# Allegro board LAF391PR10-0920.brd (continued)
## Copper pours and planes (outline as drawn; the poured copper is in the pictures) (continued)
BOOT1_ISL9538 on BOTTOM (solid shape): 31.36,42.39 31.36,41.38 31.21,41.23 31.21,40.72 31.36,40.57 31.71,40.57 31.84,40.43 31.84,39.52 31.74,39.42 30.88,39.42 30.85,39.44 30.85,40.65 30.78,40.73 30.77,40.84 30.73,40.94 30.73,41.15 31.15,41.57 31.15,42.38 31.21,42.44 31.31,42.44
BOOT2_ISL9538 on BOTTOM (solid shape): 34.54,44.47 34.85,44.47 35.02,44.3 35.02,43.57 35.06,43.57 35.12,43.51 35.66,43.51 35.72,43.45 35.72,42.55 35.72,42.53 35.03,42.53 34.93,42.64 34.93,43.04 34.7,43.27 34.7,43.55 34.75,43.74 34.7,43.93 34.7,43.95 34.54,44.11 34.46,44.11 34.37,44.12 34.28,44.11 32.67,44.11 32.62,44.15 32.62,44.28 32.68,44.35 33.95,44.35 34.07,44.47 34.31,44.47 34.32,44.47 34.37,44.47 34.43,44.48 34.54,44.48
BST_3V on BOTTOM (solid shape): 142.17,109.9 142.17,107.77 142.09,107.69 141.96,107.69 141.09,108.57 141.09,109.9 141.1,109.91 142.16,109.91
BST_5V on BOTTOM (solid shape): 45.15,45.68 45.15,44.73 45.09,44.67 44.51,44.67 44.39,44.79 44.39,45.23 44.21,45.41 43.06,45.41 42.96,45.51 42.96,45.7 43.05,45.79 45.04,45.79
BST_+1VALWP on BOTTOM (solid shape): 159.68,104.38 159.68,104.26 158.21,102.79 157.49,102.79 157.43,102.84 157.43,103.81 157.51,103.88 157.97,103.88 158.55,104.46 159.6,104.46
BST_+1VALWP_C on BOTTOM (solid shape): 156.85,103.75 156.85,102.14 156.26,101.55 155.38,101.55 155.3,101.63 155.3,102.29 155.99,102.98 155.99,103.71 156.09,103.81 156.79,103.81
CPU_B+ on BOTTOM (solid shape): 70.29,60.68 70.29,59.17 70.79,58.66 70.79,57.45 70.25,56.91 66.19,56.91 65.97,56.69 65.97,54.24 66.15,54.06 66.15,51.21 66.05,51.11 65.02,51.11 64.95,51.18 64.95,52.63 64.84,52.74 64.03,52.74 63.86,52.92 63.86,53.27 63.61,53.52 62.67,53.52 62.62,53.57 62.62,54.8 62.44,54.98 61.09,54.98 60.91,55.16 60.91,57.62 60.99,57.69 63.93,57.69 64.19,57.95 68.25,57.95 68.26,57.89 68.27,57.84 68.3,57.78 68.32,57.74 68.36,57.69 68.4,57.66 68.45,57.63 68.5,57.6 68.55,57.59 68.61,57.58 68.66,57.58 68.72,57.59 68.77,57.6 68.82,57.63 68.87,57.66 68.91,57.69 68.95,57.74 68.97,57.78 69,57.84 69.01,57.89 69.02,57.95 69.01,58 69,58.06 68.99,58.11 68.96,58.16 68.93,58.2 68.89,58.24 68.85,58.28 68.8,58.3 68.75,58.32 68.69,58.34 68.64,58.34 68.58,58.34 68.53,58.32 68.47,58.3 68.42,58.28 68.38,58.24 68.34,58.2 68.31,58.16 68.28,58.11 68.27,58.06 68.26,58 68.25,57.95 64.19,57.95 65.54,59.29 65.54,60.61 65.82,60.9 70.07,60.9
CPU_B+ on IN1 (solid shape): 66.26,56.75 66.26,51.98 66.16,51.88 64.11,51.88 63.29,52.71 63.29,56.95 63.61,57.26 65.75,57.26
CPU_B+ on IN2 (solid shape): 66.26,56.75 66.26,51.98 66.16,51.88 64.13,51.88 63.29,52.72 63.29,56.95 63.62,57.28 65.73,57.28
CPU_B+ on TOP: 72.38,84.32 73.21,85.15 74.62,85.15 75.37,85.9 82.1,85.9 84.89,88.69 87.69,88.69 87.69,87.68 85.65,87.68 82.86,84.88 76.19,84.88 75.37,84.06 75.37,78.8 75.09,78.52 72.75,78.52 72.38,78.89
CPU_B+ on TOP: 68.22,57.75 68.37,57.59 68.83,57.59 69.04,57.81 69.04,58.54 69.22,58.72 70.73,58.72 71.43,59.42 73.95,59.42 74.32,59.05 74.98,59.05 75.17,59.23 78.22,59.23 78.48,58.97 78.48,58.47 77.97,57.96 77.39,57.96 76.66,57.23 74.66,57.23 74.46,57.43 71.96,57.43 71.81,57.27 71.81,57.01 71.49,56.69 66.29,56.69 66.07,56.47 66.07,54.19 66.27,53.98 66.27,51.95 66.12,51.8 60.06,51.8 59.81,52.05 59.81,54.15 59.88,54.23 59.88,54.38 60.44,54.94 60.55,54.94 60.58,54.97 61.71,54.97 64.49,57.75
CPU_B+ on BOTTOM: 78.16,59.95 78.66,59.95 79.1,60.39 79.12,60.39 79.22,60.41 79.32,60.45 81.82,60.45 81.9,60.37 81.9,60.36 81.9,59.25 81.87,59.22 80.54,59.22 80.41,59.09 80.41,58.32 80.24,58.15 79.53,58.15 79.13,57.75 79.11,57.74 79.11,57.09 78.97,56.95 75.15,56.95 74.62,57.47 74.62,58.32 75.53,59.23 76.51,59.23 76.52,59.22 77.92,59.22 77.97,59.27 77.97,59.76
CPU_B+ on BOTTOM: 74.08,78.03 74.07,78.05 74.07,79.5 74,79.56 73.26,79.56 73.1,79.72 73.1,82.9 72.94,83.05 72.94,86.61 73.28,86.95 74.88,86.95 75.34,86.49 75.34,83.78 75.34,83.77 75.34,78.07 75.31,78.03
CPU_B+ on IN1: 73.45,78.2 73.16,78.49 73.16,81.22 73.97,82.03 74.93,82.03 75.31,81.64 75.31,78.48 75.03,78.2
CPU_B+ on IN1: 80.05,59.11 81.31,59.11 81.43,59.23 81.43,60.28 81.27,60.44 80.26,60.44 79.93,60.11 79.93,59.23
CPU_B+ on IN2: 74.73,57.34 80.76,57.34 81.44,58.02 81.44,60.22 81.22,60.44 79.89,60.44 78.71,59.25 75.22,59.25 74.41,58.45 74.41,57.66
CPU_B+ on IN2: 75.23,78.51 73.45,78.51 73.04,78.93 73.04,80.71 74.41,82.09 75.02,82.09 75.46,81.64 75.46,78.75
CPU_B+ on IN3: 64.8,53.56 66.07,53.56 66.24,53.39 66.24,51.31 66.03,51.11 64.93,51.11 64.73,51.31 64.73,53.49
CPU_B+ on IN3: 73.87,56.56 70.29,56.56 70.28,56.57 69.35,56.57 69.05,56.88 69.05,59.89 74.05,64.89 74.05,66.47 74.35,66.77 74.35,71.29 71.94,73.71 71.94,82.08 72.45,82.6 75.02,82.6 75.23,82.4 75.23,77.03 76.39,75.87 76.89,75.87 78.67,74.09 78.67,64.39 78.44,64.16 78.44,63.14 78.67,62.91 78.67,60.61 78.8,60.48 81.12,60.48 81.41,60.18 81.41,57.97 80.76,57.31 74.29,57.31 74.06,57.09 74.06,56.75
CPU_B+ on IN4: 72.59,78.42 70.79,76.63 68,76.63 66.86,75.48 64.32,75.48 63.17,76.63 61.9,76.63 56.19,70.91 56.19,60.37 57.08,59.48 63.3,59.48 63.68,59.1 63.68,55.95 63.19,55.46 63.19,52.32 64.15,51.35 66.04,51.35 66.05,51.36 66.2,51.36 66.53,51.69 66.53,52.93 66.81,53.21 66.81,56.57 67.21,56.98 70.72,56.98 71.12,57.38 79.84,57.38 81.36,58.9 81.36,60.25 81.22,60.39 80.18,60.39 79.99,60.2 78.05,60.2 77.82,59.97 76.25,59.97 76.03,60.19 76.03,60.49 75.95,60.58 69.58,60.58 68.26,61.9 65.87,61.9 63.3,64.47 63.3,71.55 62.29,72.56 62.29,73.39 62.63,73.74 67.46,73.74 67.87,73.33 71.81,73.33 74.3,75.82 74.3,77.47 74.54,77.71 75.05,77.71 75.24,77.9 75.24,81.89 74.45,82.67 73.6,82.67 72.59,81.66 ; 1 cut-out
FB_+1VALWP on BOTTOM (solid shape): 164.45,107.1 164.45,104.75 164.18,104.48 162.92,104.48 162.76,104.64 161.95,104.64 161.88,104.71 161.88,104.82 161.95,104.9 162.74,104.9 162.78,104.86 163.47,104.86 163.75,105.14 163.75,107.08 163.83,107.16 164.39,107.16
GT_SW on TOP (solid shape): 73.84,51.55 73.84,50.28 73.72,50.15 72.32,50.15 72.13,50.34 72.13,52.05 72.19,52.12 73.27,52.12
GT_SW on BOTTOM: 72.11,51.3 72.11,52.02 72.15,52.05 73.28,52.05 73.35,52.12 73.35,53.46 73.29,53.51 69.24,53.51 68.81,53.08 68.81,49.28 68.67,49.14 67.39,49.14 67.32,49.06 67.32,47.59 67.47,47.44 73.77,47.44 73.94,47.61 73.94,51.14 73.78,51.3
IA_SNUB1 on TOP (solid shape): 77.92,64.56 77.92,61.82 77.71,61.62 76.92,61.62 76.76,61.78 76.76,61.9 76.79,62.05 76.76,62.19 76.76,62.55 76.78,62.66 76.76,62.77 76.76,64.04 76.83,64.25 76.77,64.46 76.76,64.48 76.76,64.58 76.84,64.66 77.81,64.66
IA_SNUB2 on TOP (solid shape): 81.34,82.47 81.34,80.95 81.08,80.69 79.43,80.69 79.18,80.95 79.18,81.71 80.19,82.72 81.08,82.72
IA_SW1 on BOTTOM (solid shape): 82.48,67.42 82.48,66.4 82.5,66.38 83.26,66.38 83.3,66.41 83.3,67.54 83.43,67.67 84.89,67.67 85.46,67.1 85.46,63.33 85.46,63.32 85.46,61.95 85.06,61.55 84.08,61.55 83.98,61.65 83.98,62.81 83.74,63.05 80.04,63.05 79.98,63.12 79.98,64 80.11,64.14 80.11,64.14 80.31,64.35 83.2,64.35 83.21,64.29 83.22,64.24 83.24,64.18 83.27,64.14 83.31,64.09 83.35,64.06 83.4,64.03 83.45,64 83.5,63.99 83.56,63.98 83.61,63.98 83.67,63.99 83.72,64 83.77,64.03 83.82,64.06 83.86,64.09 83.89,64.14 83.92,64.18 83.94,64.24 83.96,64.29 83.97,64.35 83.96,64.4 83.95,64.46 83.93,64.51 83.91,64.56 83.88,64.6 83.84,64.64 83.79,64.68 83.75,64.71 83.69,64.73 83.64,64.74 83.58,64.74 83.53,64.74 83.47,64.73 83.42,64.71 83.37,64.68 83.33,64.64 83.29,64.6 83.26,64.56 83.23,64.51 83.21,64.46 83.2,64.4 83.2,64.35 80.31,64.35 80.73,64.76 80.79,64.82 80.79,65.78 80.8,65.82 80.8,65.88 80.8,65.95 80.79,65.98 80.79,67.07 80.79,67.07 80.79,67.45 81.02,67.67 82.22,67.67
IA_SW1 on TOP: 82.1,64.65 81.48,64.65 81.3,64.83 79.49,64.83 79.32,64.67 79.32,63.1 79.43,62.99 79.43,62.98 82.2,62.98 82.27,63.04 82.27,64.49
IA_SW2 on TOP (solid shape): 85.27,82.47 85.27,80.82 85.02,80.56 83.11,80.56 82.86,80.82 82.86,82.47 83.11,82.72 85.02,82.72
IA_SW2 on BOTTOM (solid shape): 85.27,82.9 85.27,80.44 85.02,80.18 83.37,80.18 83.32,80.23 83.32,81.8 83.3,81.82 82.51,81.82 82.51,80.47 82.1,80.06 80.89,80.06 80.32,79.48 80.32,76.38 78.8,74.87 76.69,74.87 76.56,75 76.56,75.9 77.91,75.9 78.03,76.03 78.03,80.83 78.47,81.27 78.47,82.95 78.82,83.3 84.87,83.3
INT_SPK_L+ on TOP (solid shape): 266.09,27.3 266.09,25.74 265.96,25.61 265.9,25.61 265.29,25 265.29,22.71 265.22,22.65 265.11,22.65 265.06,22.7 265.06,24.21 264.87,24.39 264.87,25.24 265.17,25.54 265.17,25.98 265.45,26.26 265.45,27.31 265.5,27.37 266.03,27.37
INT_SPK_L- on TOP (solid shape): 264.09,25.62 264.71,25 264.71,24.36 264.88,24.19 264.88,22.72 264.81,22.65 264.73,22.65 264.67,22.7 264.67,22.79 264.68,22.79 264.68,24.1 264.18,24.59 264.18,24.7 263.53,25.36 263.53,27.29 263.58,27.34 264.09,27.34
INT_SPK_R+ on TOP (solid shape): 261.25,26.61 261.19,26.41 261.25,26.21 261.26,26.2 261.26,26.17 261.48,25.94 261.48,25.67 261.71,25.44 261.75,25.4 262.51,25.4 264.09,23.83 264.09,22.71 264.03,22.65 263.93,22.65 263.86,22.72 263.86,23.72 263.17,24.41 262.65,24.41 262.16,24.9 261.23,24.9 260.75,25.38 260.75,27.29 260.8,27.35 261.25,27.35
INT_SPK_R- on TOP (solid shape): 263.36,27.3 263.36,25.28 263.93,24.71 263.93,24.64 264.49,24.08 264.49,22.71 264.42,22.65 264.33,22.65 264.27,22.7 264.27,23.85 262.68,25.44 262.68,27.32 262.72,27.36 263.31,27.36
INT_SPKR_L+ on TOP (solid shape): 267.06,28.01 267.06,26.7 266.9,26.54 266.28,26.54 266.23,26.58 266.23,27.39 266.11,27.51 265.49,27.51 265.4,27.6 265.4,28.43 265.57,28.6 266.47,28.6
INT_SPKR_L+ on BOTTOM (solid shape): 257.88,22.15 257.88,21.83 257.65,21.6 256.44,21.6 256.43,21.6 255.59,21.6 255.17,21.18 255.08,21.04 255.07,20.86 255.07,20.62 254.56,20.11 253.58,20.11 253.32,20.37 253.32,20.85 253.65,21.18 255.1,22.63 257.4,22.63
INT_SPKR_L+ on IN4 (solid shape): 256.72,22.14 256.72,21.51 256.47,21.26 255.46,21.26 255.39,21.26 255.33,21.26 255.14,21.26 254.72,21.68 254.72,21.97 255.01,22.27 256.6,22.27
INT_SPKR_L+ on IN4 (solid shape): 266.46,28.01 266.46,27.68 264.54,25.76 263.82,25.76 263.69,25.9 263.72,25.93 263.9,26.26 263.96,26.62 263.96,26.65 264.63,27.31 264.77,27.31 265.64,28.18 266.29,28.18
INT_SPKR_L- on TOP (solid shape): 264.88,28.06 264.88,26.62 264.83,26.57 264.39,26.57 264.35,26.61 264.35,27.39 264.35,27.39 264.35,27.47 264.25,27.56 263.79,27.56 263.67,27.68 263.67,27.98 263.89,28.2 264.74,28.2
INT_SPKR_L- on BOTTOM (solid shape): 257.86,20.92 257.86,20.56 257.64,20.34 256.19,20.34 255.83,20.27 255.76,19.91 254.87,19.02 254.87,18.48 254.57,18.18 253.61,18.18 253.42,18.37 253.42,19.6 253.67,19.86 254.69,19.86 255.38,20.55 255.69,20.64 255.78,20.94 256.01,21.18 257.6,21.18
INT_SPKR_L- on IN4 (solid shape): 255.45,20.24 255.45,19.99 255.07,19.6 254.41,19.6 253.5,20.52 253.5,21.08 253.55,21.13 254.56,21.13
INT_SPKR_L- on IN4 (solid shape): 264.75,28.06 264.75,27.64 264.62,27.52 264.54,27.52 263.4,26.38 263.03,26.38 262.71,26.7 262.71,26.91 263.99,28.2 264.61,28.2
INT_SPKR_R+ on TOP (solid shape): 260.64,28.33 260.64,27.56 260.52,27.44 260.52,26.63 260.43,26.54 259.82,26.54 259.55,26.81 259.55,28.34 259.73,28.52 260.45,28.52
INT_SPKR_R+ on BOTTOM (solid shape): 257.84,19.7 257.84,19.25 257.69,19.1 256.7,19.1 254.87,17.27 254.87,16.51 254.58,16.22 254.41,16.22 254.4,16.22 253.68,16.22 252.33,17.57 252.33,17.58 252.29,17.61 252.28,17.67 252.28,18.69 252.3,18.77 252.3,18.84 252.3,18.87 252.49,19.06 252.5,19.06 252.66,19.15 252.78,19.27 253.08,19.27 253.21,19.14 253.21,18.26 253.52,17.95 254.69,17.95 255.07,18.33 255.07,18.84 255.95,19.72 255.98,19.72 256.18,19.73 256.39,19.91 257.63,19.91
INT_SPKR_R+ on IN4 (solid shape): 260.64,27.99 260.64,27.58 260.48,27.43 259.98,27.43 259.36,26.81 258.58,26.81 258.36,27.03 258.36,28.02 258.45,28.11 260.51,28.11
INT_SPKR_R+ on IN4 (solid shape): 253.17,20 253.17,18.53 252.87,18.22 252.34,18.22 252.28,18.29 252.28,18.69 252.3,18.82 252.28,18.95 252.28,19.27 252.12,19.43 252.12,20.04 252.2,20.11 253.06,20.11
INT_SPKR_R- on TOP (solid shape): 263.24,28.45 263.24,27.59 263.17,27.51 262.55,27.51 262.45,27.41 262.45,26.58 262.44,26.57 261.95,26.57 261.91,26.61 261.91,27.97 261.91,27.97 261.91,28.34 262.08,28.51 263.19,28.51
INT_SPKR_R- on BOTTOM (solid shape): 251.18,19.28 251.18,18.92 251.2,18.91 251.2,18.82 252.02,17.99 252.02,17.73 252.16,17.58 252.19,17.54 252.21,17.51 253.3,16.42 253.3,16.42 253.4,16.29 253.53,16.19 253.54,16.18 253.63,16.09 253.66,16.09 254.13,15.62 254.28,15.62 254.7,15.52 254.94,15.88 254.94,15.9 254.97,15.92 254.97,16.43 255,16.45 255,17.19 256.47,18.67 257.66,18.67 257.84,18.49 257.84,18.03 257.64,17.83 256.49,17.83 255.92,17.25 255.9,17.25 255.62,17.07 255.63,16.74 255.63,16.41 255.49,16.15 255.59,15.86 255.6,15.83 255.59,15.79 255.48,15.53 255.59,15.26 255.62,15.23 255.32,14.92 255.29,14.93 254.92,14.83 254.82,14.46 254.83,14.44 254.66,14.27 254.52,14.27 254.46,14.32 253.57,14.32 253.29,14.6 253.29,14.63 253.21,14.92 252.93,15.06 252.9,15.07 252.89,15.11 252.89,15.59 252.89,15.6 252.78,16.15 252.28,16.41 251.92,16.41 251.14,17.19 251.15,17.22 251.11,17.6 250.74,17.75 250.66,17.77 250.63,17.85 250.63,19.14 250.89,19.4 251.06,19.4
INT_SPKR_R- on IN4 (solid shape): 263.19,28.38 263.19,27.71 262.99,27.5 261.75,27.5 261.65,27.61 261.65,28.61 261.8,28.75 262.82,28.75
INT_SPKR_R- on IN4 (solid shape): 251.32,19.3 251.32,18.62 251.16,18.46 250.64,18.46 250.25,18.86 249.9,18.86 249.36,19.41 249.36,20.11 249.48,20.24 250.38,20.24
LG1_ISL9538 on BOTTOM (solid shape): 33.3,41.72 33.3,41.2 33.16,41.05 32.9,41.05 32.35,41.6 32.35,42.37 32.43,42.44 32.58,42.44
LG1_ISL9538 on BOTTOM (solid shape): 34.24,33.06 34.24,32.34 34.01,32.11 31.9,32.11 31.76,32.24 31.76,32.95 31.86,33.05 33.25,33.05 33.47,33.27 34.03,33.27
LG1_ISL9538 on IN1 (solid shape): 33.46,41.45 33.46,40.04 32.69,40.04 32.69,41.56 32.82,41.69 33.22,41.69
LG1_ISL9538 on IN1 (solid shape): 34.21,33.94 34.21,32.31 34.09,32.19 33.28,32.19 32.98,32.49 32.98,33.96 33.12,34.09 34.06,34.09
LG2_ISL9538 on BOTTOM (solid shape): 34.15,42.7 34.19,42.7 34.33,42.56 34.33,42.28 34.27,42.22 34.03,42.22 33.87,42.38 33.87,42.58 33.51,42.93 32.7,42.93 32.66,42.98 32.66,43.09 32.72,43.15 33.7,43.15
LG2_ISL9538 on BOTTOM: 33.49,27.37 31.82,27.37 31.73,27.29 31.73,26.22 31.86,26.09 33.37,26.09 33.56,26.28 33.56,27.31
LG2_ISL9538 on IN1: 32.71,26.06 31.85,26.06 31.71,26.2 31.71,27.18 32.03,27.5 32.6,27.5 32.85,27.25 32.85,26.2
LG2_ISL9538 on IN1: 34.01,42.74 34.85,42.74 35.1,42.48 35.1,41.19 34.98,41.07 34.21,41.07 33.83,41.45 33.83,42.56
LX1_ISL9538 on TOP (solid shape): 39.81,36.32 39.81,34.84 39.55,34.59 38.29,34.59 38.12,34.77 38.12,36.43 38.19,36.5 39.62,36.5
LX1_ISL9538 on BOTTOM (solid shape): 32.16,42.38 32.16,41.6 33.01,40.75 33.06,40.75 33.14,40.68 33.14,40.09 33.08,40.03 32.2,40.03 31.98,40.24 31.98,40.99 31.98,41.06 31.97,41.14 31.97,41.25 31.95,41.27 31.95,42.37 32.01,42.44 32.11,42.44
LX1_ISL9538 on BOTTOM (solid shape): 41.13,39.85 41.13,32.74 40.82,32.43 35.07,32.43 34.03,33.47 32.78,33.47 32.72,33.52 32.72,36.63 33.46,37.37 33.46,37.75 34.51,37.75 34.52,37.7 34.53,37.64 34.56,37.59 34.59,37.54 34.62,37.5 34.66,37.46 34.71,37.43 34.76,37.41 34.81,37.39 34.87,37.38 34.92,37.38 34.98,37.39 35.03,37.41 35.08,37.43 35.13,37.46 35.17,37.5 35.21,37.54 35.24,37.59 35.26,37.64 35.27,37.7 35.28,37.75 35.28,37.81 35.27,37.86 35.25,37.92 35.22,37.97 35.19,38.01 35.15,38.05 35.11,38.08 35.06,38.11 35.01,38.13 34.95,38.14 34.9,38.15 34.84,38.14 34.79,38.13 34.73,38.11 34.69,38.08 34.64,38.05 34.6,38.01 34.57,37.97 34.54,37.92 34.53,37.86 34.52,37.81 34.51,37.75 33.46,37.75 33.46,38.19 33.59,38.32 36.38,38.32 36.61,38.54 36.61,39.76 36.77,39.92 41.05,39.92
LX2_ISL9538 on TOP (solid shape): 38.86,30.82 38.86,28.55 38.79,28.49 38.67,28.49 38.66,28.49 36.63,28.49 36.38,28.75 36.38,30.17 36.25,30.3 35.23,30.3 35.11,30.42 35.11,31.06 35.23,31.19 38.49,31.19
LX2_ISL9538 on BOTTOM (solid shape): 41.14,31.13 41.14,26.84 37.01,26.84 36.63,27.22 34.35,27.22 34.34,27.22 33.99,27.57 33.03,27.57 32.82,27.78 32.82,31.34 33,31.52 40.74,31.52
LX2_ISL9538 on BOTTOM (solid shape): 34.23,43.33 34.45,43.33 34.78,43.01 34.78,42.59 35.02,42.35 35.65,42.35 35.7,42.3 35.7,41.34 35.63,41.27 34.99,41.27 34.47,41.79 34.47,42.36 34.49,42.46 34.47,42.57 34.47,42.65 34.27,42.85 34.25,42.85 33.76,43.33 32.72,43.33 32.65,43.4 32.65,43.49 32.72,43.56 34,43.56
LX2_ISL9538 on IN1 (solid shape): 36.28,42.8 36.28,42.08 36.12,41.92 35.56,41.92 35.45,42.03 35.45,42.51 35.11,42.85 34.22,42.85 34.07,42.99 34.07,43.31 34.16,43.4 34.18,43.4 34.39,43.35 34.59,43.42 35.65,43.42
LX_1.8VALW on TOP (solid shape): 170.24,107.18 170.08,107.03 169.75,107.03 169.55,107.23 169.55,108.63 170.24,108.63
LX_1.8VALW on BOTTOM (solid shape): 173.71,108.53 173.92,108.53 174.25,108.2 174.25,107.79 174.07,107.62 172.57,107.62 171.93,106.98 169.73,106.98 169.46,107.24 169.46,108.53 170.27,109.34 172.9,109.34
LX_1V_PRIM on TOP (solid shape): 168.91,98.94 168.91,98.43 168.72,98.24 168.72,98.24 168.67,98.2 167.72,98.2 167.67,98.26 167.67,99.14 167.72,99.19 168.67,99.19
LX_1V_PRIM on BOTTOM (solid shape): 170.03,100.62 170.03,100.6 170.14,100.42 170.32,100.32 170.34,100.31 170.65,100 171.52,100 171.58,99.94 171.58,99.89 171.58,99.3 171.52,99.24 170.23,99.24 169.42,98.43 167.73,98.43 167.54,98.63 167.54,100.59 167.73,100.78 169.87,100.78
LX_1VS_VCCIO on BOTTOM (solid shape): 173.05,51.91 173.05,51.02 173.24,50.84 174.06,50.84 174.13,50.77 174.13,50.14 174.05,50.07 173.19,50.07 172.85,49.73 172.85,48.15 172.78,48.08 171.75,48.08 171.47,48.37 171.47,51.9 171.58,52.02 172.95,52.02
LX_3V on TOP (solid shape): 139.63,109.27 139.63,108.25 139.5,108.12 137.34,108.12 137.22,108.25 137.22,109.27 137.34,109.39 139.5,109.39
LX_3V on BOTTOM (solid shape): 144.96,108.7 144.96,107.43 144.9,107.36 144.17,107.36 144.07,107.46 144.07,107.55 144.2,107.68 144.2,108.7 144.33,108.82 144.84,108.82
LX_3V on BOTTOM (solid shape): 140.83,109.97 140.83,108.44 141.76,107.51 141.76,106.96 141.72,106.92 140.14,106.92 139.82,106.6 139.82,104.31 139.76,104.25 137.41,104.25 137.22,104.44 137.22,109.65 137.6,110.03 140.77,110.03
LX_3V on IN2 (solid shape): 144.96,108.7 144.96,108.06 144.58,107.68 140.14,107.68 140.01,107.81 140.01,108.57 140.14,108.7 141.12,108.7 141.47,108.47 141.82,108.7 144.14,108.7 144.33,108.89 144.77,108.89
LX_5V on TOP (solid shape): 45.39,47.89 45.39,46.15 45.14,45.89 43.49,45.89 43.16,46.22 43.16,47.24 43.59,47.67 43.59,47.87 43.69,47.97 45.31,47.97
LX_5V on BOTTOM (solid shape): 45.32,49.88 45.32,46.17 45.15,46 42.98,46 42.83,45.84 42.78,45.84 42.77,45.85 42.55,45.92 42.33,45.85 42.32,45.84 42.27,45.84 42.19,45.92 42.19,47.67 42.02,47.84 41.5,47.84 41.41,47.93 41.41,49.99 41.52,50.1 45.09,50.1
LX_5V on IN1 (solid shape): 44.21,46.64 44.21,43.97 43.71,43.47 43.66,43.43 43.63,43.39 43.53,43.3 43.53,42.39 43.48,42.33 42.75,42.33 42.6,42.49 42.6,43.3 43.16,43.86 43.16,46.54 43.31,46.7 44.15,46.7
LX_DDR on BOTTOM (solid shape): 52.84,60.68 52.84,60.42 52.99,60.27 55.45,60.27 55.53,60.19 55.53,59.03 55.45,58.95 53.5,58.95 52.63,58.09 52.63,55.33 52.15,54.85 48.96,54.85 48.75,55.06 48.75,58.11 49.78,59.14 49.78,60.31 49.9,60.43 51.42,60.43 51.87,60.88 52.63,60.88
Net_123 on GND3 (solid shape): 276.13,77.43 275.23,76.53 274.33,77.43 275.23,78.32
Net_124 on VCC (solid shape): 276.13,77.43 275.23,76.53 274.33,77.43 275.23,78.32
Net_125 on GND2 (solid shape): 276.13,77.43 275.23,76.53 274.33,77.43 275.23,78.32
Net_126 on GND1 (solid shape): 276.13,77.43 275.23,76.53 274.33,77.43 275.23,78.32
Net_127 on GND3 (solid shape): 274.33,79.22 273.43,78.32 272.53,79.22 273.43,80.12
Net_128 on VCC (solid shape): 274.33,79.22 273.43,78.32 272.53,79.22 273.43,80.12
Net_129 on GND2 (solid shape): 274.33,79.22 273.43,78.32 272.53,79.22 273.43,80.12
Net_130 on GND1 (solid shape): 274.33,79.22 273.43,78.32 272.53,79.22 273.43,80.12
Net_131 on GND3 (solid shape): 272.53,81.02 271.64,80.12 270.74,81.02 271.64,81.92
Net_132 on VCC (solid shape): 272.53,81.02 271.64,80.12 270.74,81.02 271.64,81.92
Net_133 on GND2 (solid shape): 272.53,81.02 271.64,80.12 270.74,81.02 271.64,81.92
Net_134 on GND1 (solid shape): 272.53,81.02 271.64,80.12 270.74,81.02 271.64,81.92
Net_135 on GND3 (solid shape): 270.74,82.81 269.84,81.92 268.94,82.81 269.84,83.71
Net_136 on VCC (solid shape): 270.74,82.81 269.84,81.92 268.94,82.81 269.84,83.71
Net_137 on GND2 (solid shape): 270.74,82.81 269.84,81.92 268.94,82.81 269.84,83.71
Net_138 on GND1 (solid shape): 270.74,82.81 269.84,81.92 268.94,82.81 269.84,83.71
Net_139 on GND3 (solid shape): 264.98,86.79 263.71,86.79 263.71,88.06 264.98,88.06
Net_140 on VCC (solid shape): 264.98,86.79 263.71,86.79 263.71,88.06 264.98,88.06
Net_141 on GND2 (solid shape): 264.98,86.79 263.71,86.79 263.71,88.06 264.98,88.06
Net_142 on GND1 (solid shape): 264.98,86.79 263.71,86.79 263.71,88.06 264.98,88.06
Net_143 on GND3 (solid shape): 264.98,89.33 263.71,89.33 263.71,90.6 264.98,90.6
Net_144 on VCC (solid shape): 264.98,89.33 263.71,89.33 263.71,90.6 264.98,90.6
Net_145 on GND2 (solid shape): 264.98,89.33 263.71,89.33 263.71,90.6 264.98,90.6
Net_146 on GND1 (solid shape): 264.98,89.33 263.71,89.33 263.71,90.6 264.98,90.6
Net_147 on GND3 (solid shape): 264.98,91.87 263.71,91.87 263.71,93.14 264.98,93.14
Net_148 on VCC (solid shape): 264.98,91.87 263.71,91.87 263.71,93.14 264.98,93.14
Net_149 on GND2 (solid shape): 264.98,91.87 263.71,91.87 263.71,93.14 264.98,93.14
Net_150 on GND1 (solid shape): 264.98,91.87 263.71,91.87 263.71,93.14 264.98,93.14
Net_151 on GND3 (solid shape): 264.98,94.41 263.71,94.41 263.71,95.68 264.98,95.68
Net_152 on VCC (solid shape): 264.98,94.41 263.71,94.41 263.71,95.68 264.98,95.68
Net_153 on GND2 (solid shape): 264.98,94.41 263.71,94.41 263.71,95.68 264.98,95.68
Net_154 on GND1 (solid shape): 264.98,94.41 263.71,94.41 263.71,95.68 264.98,95.68
Net_160 on IN4 (solid shape): 276.13,77.43 275.23,76.53 274.33,77.43 275.23,78.32
Net_161 on IN3 (solid shape): 276.13,77.43 275.23,76.53 274.33,77.43 275.23,78.32
Net_162 on IN2 (solid shape): 276.13,77.43 275.23,76.53 274.33,77.43 275.23,78.32
Net_163 on IN1 (solid shape): 276.13,77.43 275.23,76.53 274.33,77.43 275.23,78.32
Net_164 on IN4 (solid shape): 274.33,79.22 273.43,78.32 272.53,79.22 273.43,80.12
Net_165 on IN3 (solid shape): 274.33,79.22 273.43,78.32 272.53,79.22 273.43,80.12
Net_166 on IN2 (solid shape): 274.33,79.22 273.43,78.32 272.53,79.22 273.43,80.12
Net_167 on IN1 (solid shape): 274.33,79.22 273.43,78.32 272.53,79.22 273.43,80.12
Net_168 on IN4 (solid shape): 272.53,81.02 271.64,80.12 270.74,81.02 271.64,81.92
Net_169 on IN3 (solid shape): 272.53,81.02 271.64,80.12 270.74,81.02 271.64,81.92
Net_170 on IN2 (solid shape): 272.53,81.02 271.64,80.12 270.74,81.02 271.64,81.92
Net_171 on IN1 (solid shape): 272.53,81.02 271.64,80.12 270.74,81.02 271.64,81.92
Net_172 on IN4 (solid shape): 270.74,82.81 269.84,81.92 268.94,82.81 269.84,83.71
Net_173 on IN3 (solid shape): 270.74,82.81 269.84,81.92 268.94,82.81 269.84,83.71
Net_174 on IN2 (solid shape): 270.74,82.81 269.84,81.92 268.94,82.81 269.84,83.71
Net_175 on IN1 (solid shape): 270.74,82.81 269.84,81.92 268.94,82.81 269.84,83.71
Net_178 on IN4 (solid shape): 264.98,86.79 263.71,86.79 263.71,88.06 264.98,88.06
Net_179 on IN3 (solid shape): 264.98,86.79 263.71,86.79 263.71,88.06 264.98,88.06
Net_180 on IN2 (solid shape): 264.98,86.79 263.71,86.79 263.71,88.06 264.98,88.06
Net_181 on IN4 (solid shape): 264.98,89.33 263.71,89.33 263.71,90.6 264.98,90.6
Net_182 on IN3 (solid shape): 264.98,89.33 263.71,89.33 263.71,90.6 264.98,90.6
Net_183 on IN2 (solid shape): 264.98,89.33 263.71,89.33 263.71,90.6 264.98,90.6
Net_184 on IN4 (solid shape): 264.98,91.87 263.71,91.87 263.71,93.14 264.98,93.14
Net_185 on IN3 (solid shape): 264.98,91.87 263.71,91.87 263.71,93.14 264.98,93.14
Net_186 on IN2 (solid shape): 264.98,91.87 263.71,91.87 263.71,93.14 264.98,93.14
Net_187 on IN4 (solid shape): 264.98,94.41 263.71,94.41 263.71,95.68 264.98,95.68
Net_188 on IN3 (solid shape): 264.98,94.41 263.71,94.41 263.71,95.68 264.98,95.68
Net_189 on IN2 (solid shape): 264.98,94.41 263.71,94.41 263.71,95.68 264.98,95.68
Net_190 on IN1 (solid shape): 264.98,86.79 263.71,86.79 263.71,88.06 264.98,88.06
Net_191 on IN1 (solid shape): 264.98,89.33 263.71,89.33 263.71,90.6 264.98,90.6
Net_192 on IN1 (solid shape): 264.98,91.87 263.71,91.87 263.71,93.14 264.98,93.14
Net_193 on IN1 (solid shape): 264.98,94.41 263.71,94.41 263.71,95.68 264.98,95.68
PBATT+_C on TOP (solid shape): 47.18,26.37 47.18,23.85 46.74,23.41 45.39,23.41 45.2,23.22 45.2,21.48 44.98,21.26 41.08,21.26 40.89,21.44 40.89,22.9 41.01,23.02 41.01,24.29 42.81,26.08 45.27,26.08 46.02,26.83 46.73,26.83
PBATT+_C on BOTTOM (solid shape): 45.19,25.9 45.19,24.35 45.01,24.18 42.35,24.18 42.16,23.99 42.16,22.84 42.35,22.65 43.36,22.65 43.74,22.27 43.74,21.51 43.11,20.87 38.28,20.87 37.9,21.26 37.9,25.45 38.54,26.08 45.01,26.08
RING2 on TOP (solid shape): 269.57,19.5 269.57,19.17 269.46,19.06 269.2,19.06 268.52,19.75 267.64,19.75 267.58,19.81 267.58,19.91 267.63,19.96 268.48,19.96 268.51,19.98 269.08,19.98
RING2 on TOP (solid shape): 273.14,17.14 273.97,17.14 274.04,17.07 274.04,16.57 273.95,16.48 271.88,16.48 271.83,16.43 271.2,16.43 271.15,16.48 271.15,17 271.2,17.06 271.9,17.06 272.32,17.48 272.81,17.48
RING2 on IN2 (solid shape): 273.2,17.85 273.2,16.73 273.1,16.64 271.71,16.64 271.58,16.77 271.58,17.9 271.67,17.98 271.7,17.99 273.06,17.99
RING2 on IN2 (solid shape): 270.71,19.91 270.71,19.01 270.59,18.9 268.81,18.9 268.66,19.05 268.66,19.89 268.83,20.06 270.57,20.06
RING2_R on TOP (solid shape): 282.36,10.19 282.36,9.04 281.96,8.63 280.49,8.63 280.14,8.99 280.13,8.99 279.99,9.13 279.98,9.14 279.92,9.2 279.54,9.2 279.35,9.39 279.35,10.21 279.65,10.51 282.04,10.51
RING2_R on TOP (solid shape): 276.99,16.46 276.99,15.38 276.86,15.25 276.14,15.25 275.28,16.1 274.99,16.1 274.68,15.79 273.94,15.79 273.87,15.8 273.8,15.79 273.23,15.79 273.19,15.83 273.19,16.26 273.27,16.34 274.16,16.34 274.48,16.67 276.78,16.67
RING2_R on IN2 (solid shape): 282.18,9.93 282.18,8.82 281.94,8.58 280.39,8.58 280.14,8.84 280.14,9.97 280.4,10.24 281.87,10.24
RING2_R on IN2 (solid shape): 296.68,13.31 296.68,11.77 296.57,11.66 294.97,11.66 294.8,11.83 294.8,12.23 294.01,13.03 294.01,13.71 294.06,13.76 296.23,13.76
SA_LGATE on BOTTOM: 88.7,85.39 88.32,85.39 88.19,85.26 88.19,84.65 88.32,84.53 88.42,84.53 89.21,83.74 89.59,83.74 89.84,83.99 89.84,84.07 89.87,84.1 89.87,84.25 89.74,84.37 89.26,84.37 88.83,84.81 88.83,85.26
SA_SNUB on TOP (solid shape): 94.67,83.74 94.67,82.8 94.58,82.71 91.96,82.71 91.88,82.79 91.88,83.74 92,83.87 94.54,83.87
SA_SW on TOP (solid shape): 94.67,87.55 94.67,85.39 94.54,85.26 93.02,85.26 92.89,85.39 92.89,86.47 93.15,86.72 93.15,87.52 93.43,87.8 94.42,87.8
SA_SW on BOTTOM (solid shape): 92.84,87.8 92.94,87.79 93.04,87.8 94.42,87.8 94.67,87.55 95.18,87.55 95.31,87.42 95.31,86.41 95.18,86.28 94.29,86.28 94.29,85.39 94.42,85.26 95.18,85.26 95.31,85.14 95.31,83.99 94.29,82.98 92.51,82.98 92.13,83.36 92.13,84.37 91.95,84.55 89.34,84.55 89.21,84.68 89.21,85.52 89.34,85.64 92.13,85.64 92.38,85.9 92.38,87.4 92.79,87.8
SA_SW on BOTTOM: 86.67,84.5 86.16,85.01 85.12,85.01 84.99,85.14 84.99,85.72 85.12,85.85 86.47,85.85 86.57,85.75 86.57,85.51 86.75,85.33 86.92,85.33 86.99,85.26 86.99,84.57 86.92,84.5
SA_UGATE on BOTTOM: 86.54,87.58 86.92,87.58 87.05,87.45 87.05,86.84 86.97,86.76 86.59,86.76 86.52,86.69 86.52,86.05 86.44,85.98 86.08,85.98 86.03,86.03 86.03,86.38 86.15,86.5 86.15,87.18
SLEEVE on TOP (solid shape): 270.66,19.37 270.66,18.95 270.83,18.77 271.36,18.77 271.67,18.47 273.03,18.47 273.16,18.6 273.98,18.6 274.03,18.56 274.03,18.11 273.87,17.95 273.84,17.95 273.61,17.73 272.21,17.73 271.79,17.31 271.19,17.31 271.03,17.47 271.03,17.91 270.88,18.05 270.31,18.05 269.94,18.42 269.94,18.44 269.88,18.58 269.75,18.68 269.72,18.69 269.72,19.54 269.12,20.14 267.65,20.14 267.58,20.21 267.58,20.3 267.64,20.37 269.66,20.37
SLEEVE_R on TOP (solid shape): 294.52,13.1 294.52,11.86 294.32,11.66 292.47,11.66 292.21,11.92 292.21,13.27 292.39,13.45 294.17,13.45
SLEEVE_R on TOP (solid shape): 285.04,12.45 285.04,11.78 284.78,11.52 282.9,11.52 282.56,11.18 280.85,11.18 280.48,10.81 279.77,10.81 279.59,11 279.59,12.27 279.8,12.48 281.48,12.48 281.62,12.62 284.88,12.62
SLEEVE_R on TOP (solid shape): 276.47,19.38 276.47,18.6 276.32,18.45 276.2,18.45 275.88,18.77 275.8,18.77 275.79,18.77 274.2,18.77 274.12,18.86 273.18,18.86 273.13,18.9 273.13,19.32 273.21,19.4 273.87,19.4 273.99,19.52 276.33,19.52
SLEEVE_R on IN4 (solid shape): 280.68,12.06 280.68,11.07 280.49,10.88 279.13,10.88 278.89,11.12 278.89,12.05 279.07,12.22 280.51,12.22
SLEEVE_R on IN4 (solid shape): 276.74,19.38 276.74,18.41 276.61,18.29 274.93,18.29 274.72,18.5 274.72,19.22 275.02,19.53 276.59,19.53
SNB_+1VALWP on TOP (solid shape): 158.99,103.56 158.99,102.4 158.44,101.85 156.37,101.85 156.23,101.99 156.23,102.93 156.38,103.08 157.8,103.08 158.34,103.61 158.94,103.61
SNUB_1VS_VCCIO on BOTTOM (solid shape): 171.17,48.99 171.17,48.15 171.12,48.1 170.39,48.1 170.39,48.21 170.16,48.43 169.7,48.43 169.68,48.46 169.68,48.99 169.71,49.02 171.15,49.02
SW_+1VALWP on TOP (solid shape): 156.68,101.37 157.5,101.37 158.01,100.86 158.01,99.32 157.91,99.22 156.35,99.22 155.95,99.62 155.95,101.21 156.12,101.38 156.67,101.38
SW_+1VALWP on BOTTOM (solid shape): 160,107.17 160,106.39 159.94,106.32 159.82,106.32 159.76,106.38 159.23,106.38 159.08,106.52 159.08,107.32 159.25,107.49 159.69,107.49
SW_+1VALWP on BOTTOM (solid shape): 160.45,104.04 160.45,98.67 160.15,98.37 155.76,98.37 155.35,98.78 155.35,100.8 155.43,100.88 156.28,100.88 156.28,101.38 157.08,101.38 159.82,104.12 160.37,104.12
SW_+1VALWP on IN1 (solid shape): 159.65,107.33 159.65,105.44 159.4,105.19 158.7,105.19 158.41,105.48 158.41,107.21 158.66,107.46 159.52,107.46
SW_+1VALWP on IN1 (solid shape): 157.88,101.66 157.88,101.29 156.95,100.36 156.82,100.36 156.18,100.99 156.18,101.2 157.13,102.15 157.39,102.15
TBTA_CC1 on BOTTOM: 13.31,72.46 10.85,72.46 10.8,72.44 10.67,72.31 10.67,72.18 10.82,72.03 10.85,72.03 10.98,72.16 13.29,72.16 13.39,72.06 13.52,72.06 13.62,72.16 13.62,72.49 13.54,72.56 13.42,72.56
TBTA_CC2 on BOTTOM: 13.34,71.95 10.93,71.95 10.65,71.67 10.65,71.47 10.77,71.34 10.98,71.34 11.31,71.67 12.96,71.67 13.24,71.4 13.42,71.4 13.47,71.45 13.47,71.83
UG1_ISL9538 on IN1 (solid shape): 31.83,41.25 31.83,39.99 31.48,39.64 30.87,39.64 30.69,39.82 30.69,40.51 30.78,40.75 30.69,40.99 30.69,41.17 30.94,41.42 31.66,41.42
UG1_ISL9538 on BOTTOM: 28.05,32.85 27.09,32.85 26.92,32.68 26.92,31.71 27.04,31.6 27.89,31.6 28.05,31.76
UG1_ISL9538 on IN1: 28.18,31.54 27.04,31.54 26.87,31.7 26.87,32.42 27.28,32.83 28.23,32.83 28.37,32.69 28.37,31.72
UG2_ISL9538 on BOTTOM (solid shape): 28.1,26.64 28.18,26.57 29.08,26.57 29.13,26.51 29.13,25.99 29.06,25.92 27.4,25.92 27.32,25.99 27.32,27.27 27.44,27.39 28.1,27.39
UG2_ISL9538 on IN1 (solid shape): 29.87,26.44 29.87,25.68 29.78,25.59 28.21,25.59 28.03,25.77 28.03,26.41 28.21,26.59 29.72,26.59
UG2_ISL9538 on IN1 (solid shape): 36.68,43.96 36.7,43.96 36.86,43.89 37.04,43.91 37.39,43.55 37.39,42.84 37.16,42.61 36.82,42.61 36.71,42.72 36.71,42.82 35.79,43.73 34.65,43.73 34.47,43.55 34.2,43.55 34.01,43.75 34.01,44.18 34.3,44.47 36.17,44.47
N16399089 on TOP (solid shape): outline of 105 points within 24.61,37.12 29.48,41.64
N16775513 on BOTTOM (solid shape): 52.67,63.16 52.67,62.22 52.81,62.09 52.81,61.21 52.63,61.03 52.07,61.03 51.9,61.21 51.9,63.07 52.02,63.19 52.64,63.19
N16775517 on BOTTOM (solid shape): 54.21,62.99 54.21,62.14 54.21,62.14 54.21,62.08 54.17,61.92 54.21,61.76 54.21,60.85 54.13,60.78 53.52,60.78 53.32,60.98 53.32,63.09 53.45,63.22 53.99,63.22
N16783126 on BOTTOM: 140.96,106.28 141.72,106.28 141.79,106.22 141.79,104.69 140.77,103.68 140.77,102.47 140.64,102.35 140.07,102.35 139.37,101.65 137.98,101.65 137.91,101.71 137.91,102.28 138.17,102.54 139.25,102.54 139.44,102.73 139.44,103.55 140.71,104.82 140.71,106.03
N16784595 on BOTTOM (solid shape): 142.04,111.3 142.04,110.65 141.99,110.6 141.18,110.6 140.99,110.41 140.01,110.41 139.88,110.54 139.88,111.3 140.01,111.43 141.91,111.43
N35551696 on TOP (solid shape): 42.51,68.73 42.51,65.01 42.19,64.7 40.52,64.7 40.47,64.75 40.47,65.84 40.48,65.85 40.48,66.59 40.38,66.7 40.38,66.7 40.29,66.83 40.17,66.91 40.16,66.91 40.07,67 39.25,67 39.18,67.06 39.18,67.57 39.25,67.64 39.87,67.64 40.19,67.95 40.19,68.64 40.49,68.94 42.3,68.94
N36626863 on TOP (solid shape): 19.83,67.15 19.83,66.53 19.69,66.39 18.08,66.39 17.95,66.51 17.16,66.51 16.99,66.69 16.99,67.21 17.05,67.28 17.05,67.28 17.13,67.36 19.63,67.36
N45988164 on BOTTOM (solid shape): 40.73,48.17 40.73,47.16 40.96,46.94 41.28,46.94 41.54,46.68 41.54,45.8 41.48,45.74 40.92,45.74 40.81,45.85 40.81,46.01 40.31,46.51 40.13,46.51 39.96,46.67 39.96,48.21 40.03,48.28 40.62,48.28
N47324022 on BOTTOM (solid shape): 161.8,104.05 161.8,104.03 162.76,103.08 164.25,103.08 164.32,103.01 164.32,102.19 164.25,102.11 162.28,102.11 161.09,103.3 161.09,104.05 161.17,104.13 161.73,104.13
N49223737 on BOTTOM (solid shape): 80.87,58.85 80.87,58.13 80.32,57.59 80.32,57.06 80.2,56.94 79.38,56.94 79.28,57.04 79.28,57.65 79.63,58 80.3,58 80.55,58.26 80.55,58.82 80.64,58.91 80.8,58.91
N49223739 on BOTTOM (solid shape): 81.88,58.87 81.88,57.91 81.57,57.6 81.57,57.1 81.48,57.02 80.92,57.02 80.91,57.02 80.69,57.02 80.68,57.01 80.63,57.01 80.57,57.07 80.57,57.63 80.96,58.02 81.34,58.02 81.55,58.23 81.55,58.86 81.64,58.95 81.81,58.95
N49223741 on BOTTOM (solid shape): 81.56,56.43 81.56,55.68 81.48,55.59 79.41,55.59 79.33,55.67 79.33,56.51 79.41,56.59 81.4,56.59
N49227484 on BOTTOM: 72.65,79.06 72.26,79.46 72.26,81.78 72.04,82 71.23,82 71.13,82.1 71.13,82.91 71.21,82.99 72.61,82.99 72.96,82.64 72.96,79.61 73.18,79.39 73.8,79.39 73.87,79.32 73.87,79.12 73.81,79.06
N49227486 on BOTTOM: 72.56,78.05 72.18,78.43 71.11,78.43 71.02,78.52 71.02,79.16 71.13,79.26 72.18,79.26 73.06,78.39 73.78,78.39 73.87,78.3 73.87,78.11 73.81,78.05
N49227488 on BOTTOM: 71.14,79.86 72.06,79.86 72.1,79.9 72.1,81.48 72.03,81.56 71.1,81.56 71.03,81.48 71.03,79.97
N49231017 on BOTTOM: 63.29,51.08 62.66,51.08 62.6,51.14 62.6,52.02 62.67,52.09 63.49,52.09 63.99,51.59 64.64,51.59 64.76,51.47 64.76,51.32 64.68,51.24 63.45,51.24
N49231019 on BOTTOM: 63.98,52.58 64.68,52.58 64.76,52.49 64.76,52.26 64.72,52.22 62.51,52.22 62.47,52.27 62.47,53.28 62.57,53.39 63.53,53.39 63.66,53.25 63.66,52.9
N50204886 on BOTTOM (solid shape): 33.14,39.26 33.14,38.38 32.78,38.02 30.73,38.02 30.73,38.85 30.79,38.91 31.56,38.91 32.05,39.39 33.01,39.39
N51859224 on TOP (solid shape): 258.55,70.86 258.55,70.55 258.5,70.45 258.48,70.34 258.48,69.92 258.55,69.85 258.55,69.71 259.26,69 259.26,67.67 259.39,67.55 259.39,66.72 257.21,66.72 257.16,66.77 257.16,67.49 257.4,67.73 258.12,67.73 258.41,68.03 258.41,68.88 257.92,69.38 257.92,70.81 257.98,70.87 258.54,70.87

Small or netless copper shapes (teardrops, artwork), in the pictures only: 178 on TOP, 64 on BOTTOM, 1 on IN2, 1 on IN3

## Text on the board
Ref Des/Silkscreen Bottom: H34 | H7 | H8 | 2 | 1 | 3 | PWB P/N:K0PFN | REV:A00 | COPYRIGHT 2017 | ALL RIGHT RESERVED
User.Comments: LA-F391P | 2018-09-20 | 2017-09-20 | Minjia | DDM60
Ref Des/Silkscreen Top: A
USER_PART_NUM_TOP: L7 | L8 | L9 | L10 | VCC | IN3 | IN4 | LS-XXXXP | GND3 | IN2 | GND2 | TOP | GND1 | IN1 | BOT
User.21: IMPEDANCE
User.39: trace Width | Width/space | 7.7 | 5.6 | 6.6 | 3.5 | 4.8 | 4 | 3.6 / 3.5 | 3.9 / 3.5 | 3.5 / 3.6 | 4.8 / 4.3 | 3.7 / 3.6 | 3.5 / 4.9 | 4 / 5.7 | 3.5 / 8.3 | 3 / 6.5 | 9 / 4.5 | SB_1_2mm-10L_WithOutC_151106 | L1-TOP | L2-GND1 | L3-IN1 | L4-GND2 | L5-IN2 | L6-IN3 | L7-VCC | L8-IN4 | L9-GND3 | L10-BOT | LAYER | NAME | STACKUP: 10 LAYER | 39 ohm | 50 ohm | 83 ohm | THICKNESS=1.2mm | Impedance | 85 ohm | 90 ohm | 100 ohm | No Ref
User.40: FIGURE | SIZE | 8.0 | 22.0 | 28.0 | 35.0 | 39.0 | 83.0 | 110.0 | 118.0 | 126.0 | 130.0 | 150.0 | 31.0 | 40.0 | 43.0 | 63.0 | 47.0x16.0 | 49.0x28.0 | 55.0x24.0 | 55.0x28.0 | 59.0x28.0 | 63.0x31.0 | 67.0x28.0 | 75.0x24.0 | 94.0x28.0 | 94.0x43.0 | 102.0x31.0 | 142.0x83.0 | 205.0x165.0 | DRILL CHART: TOP to BOTTOM | ALL UNITS ARE IN MILS | TOLERANCE | +3.0/-3.0 | +2.0/-2.0 | PLATED | NON-PLATED | QTY | 6085 | 19 | 33 | 10 | 5 | 1 | 8 | 3 | 2 | 4 | 6 | 7
